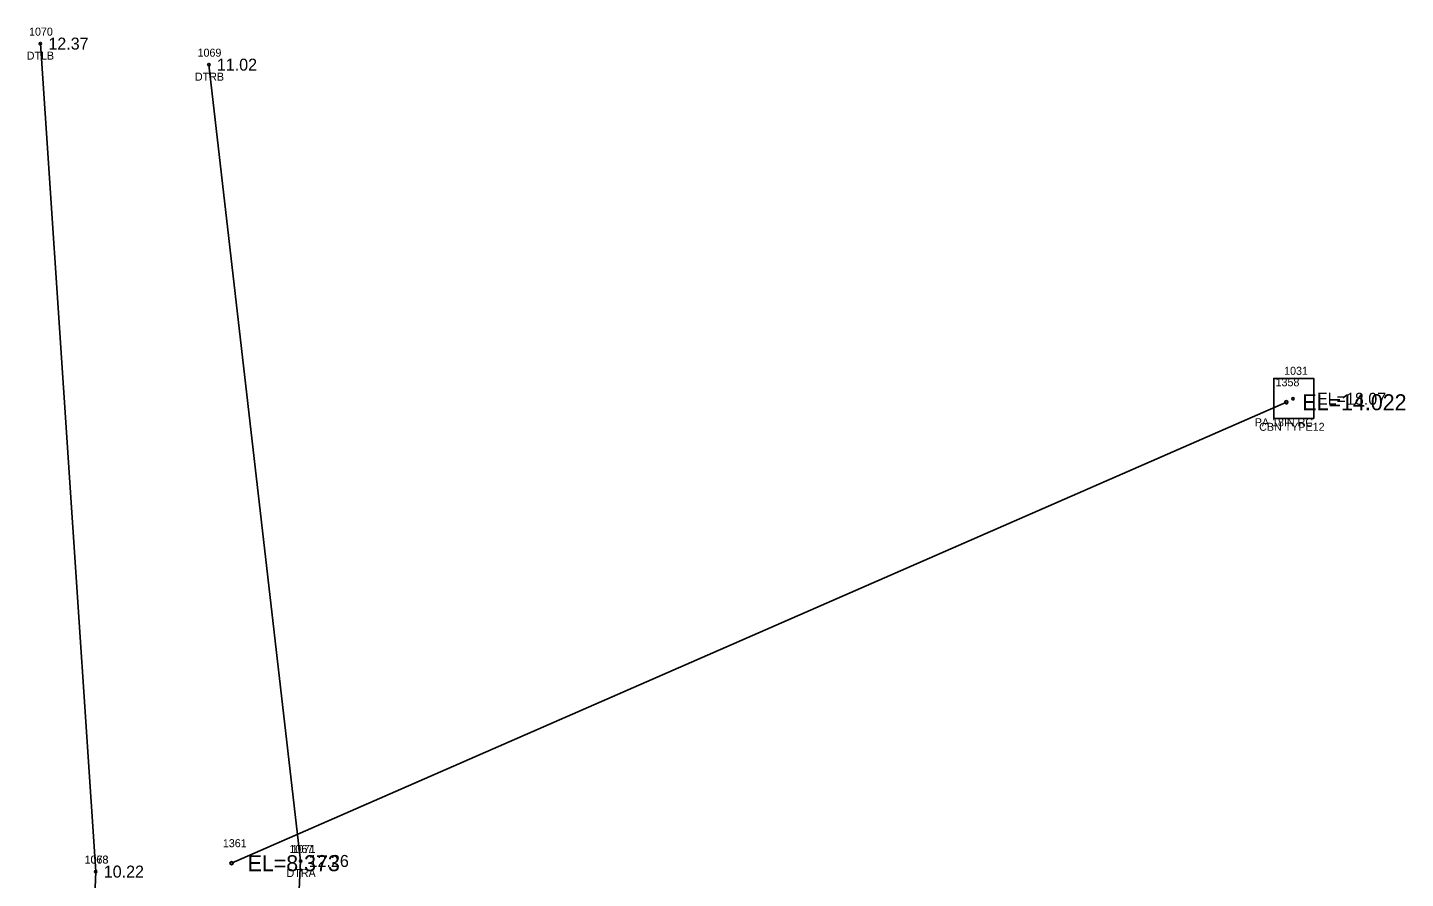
# Model space of a CAD drawing. Extents: x 2072307 to 2072993, y 127574 to 129736.
# Drawn here: x 2072396.9 to 2072569, y 129473 to 129579.4 of the extents above; entities that cross this region are included whole.
import ezdxf

# ---------------------------------------------------------------- set-up
doc = ezdxf.new("R2010")
doc.units = 0
for name, color, linetype in [('RD_EX_DR_Inlet', 7, 'Continuous'), ('RD_EX_DR_Inlet_txCode', 7, 'Continuous'), ('RD_EX_DR_Pipe', 7, 'Continuous'), ('RD_EX_DR_Pipe_txCode', 7, 'Continuous'), ('RD_EX_H2O', 7, 'Continuous'), ('RD_EX_H2O_txCode', 7, 'Continuous'), ('RD_EX_TX_DR_Inlet_ELEV', 7, 'Continuous'), ('RD_EX_TX_H2O_ELEV', 7, 'Continuous'), ('RD_SMD_Locator', 7, 'Continuous'), ('RD_TX_Pipe_ElevEX', 7, 'Continuous')]:
    doc.layers.add(name, color=color, linetype=linetype)

msp = doc.modelspace()

# ---------------------------------------------------------------- linework, layer by layer
at = {"layer": 'RD_EX_DR_Inlet'}
msp.add_line((2072557.59, 129530.55), (2072557.59, 129535.55), dxfattribs=at)
msp.add_lwpolyline([(2072557.59, 129530.55), (2072557.59, 129535.55), (2072552.59, 129535.55), (2072552.59, 129530.55)], close=True, dxfattribs=at)
at = {"layer": 'RD_EX_DR_Pipe'}
msp.add_line((2072554.17, 129532.57), (2072422.36, 129474.95), dxfattribs=at)
at = {"layer": 'RD_EX_H2O'}
for p, q in [((2072405.39, 129473.9), (2072398.47, 129577.4)), ((2072430.99, 129475.23), (2072419.52, 129574.77))]:
    msp.add_line(p, q, dxfattribs=at)
for points in [[(2072430.99, 129475.23), (2072426.01, 129368.3), (2072422.66, 129295.95), (2072416.7, 129153.3), (2072414.39, 129056.34)], [(2072405.39, 129473.9), (2072401.06, 129369.87), (2072405.35, 129295.82), (2072402.29, 129156.96), (2072397.22, 129166.67)]]:
    msp.add_lwpolyline(points, dxfattribs=at)
at = {"layer": 'RD_SMD_Locator'}
for centre, radius in [((2072398.47, 129577.4), 0.15), ((2072419.52, 129574.77), 0.15), ((2072554.17, 129532.57), 0.2), ((2072554.99, 129533), 0.15), ((2072430.99, 129475.23), 0.15), ((2072430.99, 129475.23), 0.15), ((2072405.39, 129473.9), 0.15), ((2072405.39, 129473.9), 0.15), ((2072422.36, 129474.95), 0.2)]:
    msp.add_circle(centre, radius, dxfattribs=at)

# ---------------------------------------------------------------- texts
at = {"layer": 'RD_EX_DR_Inlet_txCode'}
for s, p in [('1031', (2072553.89, 129536)), ('CBN TYPE12', (2072550.77, 129529))]:
    msp.add_text(s, height=1, dxfattribs=at).set_placement(p)
at = {"layer": 'RD_EX_DR_Pipe_txCode'}
for s, p in [('1358', (2072552.82, 129534.57)), ('PA 18IN RC', (2072550.22, 129529.57)), ('1361', (2072421.27, 129476.95))]:
    msp.add_text(s, height=1, dxfattribs=at).set_placement(p)
at = {"layer": 'RD_EX_H2O_txCode'}
for s, p in [('1070', (2072397.05, 129578.4)), ('DTLB', (2072396.76, 129575.4)), ('1069', (2072418.11, 129575.77)), ('DTRB', (2072417.78, 129572.77)), ('1067', (2072429.58, 129476.23)), ('1071', (2072429.88, 129476.23)), ('1068', (2072403.98, 129474.9)), ('1073', (2072404.01, 129474.9)), ('DTRA', (2072429.23, 129473.23)), ('DTRA', (2072429.23, 129473.23))]:
    msp.add_text(s, height=1, dxfattribs=at).set_placement(p)
at = {"layer": 'RD_EX_TX_DR_Inlet_ELEV'}
msp.add_text('EL=18.07', height=1.5, dxfattribs=at).set_placement((2072557.99, 129532.25))
at = {"layer": 'RD_EX_TX_H2O_ELEV'}
for s, p in [('12.37', (2072399.47, 129576.65)), ('11.02', (2072420.52, 129574.02)), ('12.26', (2072431.99, 129474.48)), ('12.26', (2072431.99, 129474.48)), ('10.22', (2072406.39, 129473.15)), ('10.22', (2072406.39, 129473.15))]:
    msp.add_text(s, height=1.5, dxfattribs=at).set_placement(p)
at = {"layer": 'RD_TX_Pipe_ElevEX'}
for s, p in [('EL=14.022', (2072556.17, 129531.57)), ('EL=8.373', (2072424.36, 129473.95))]:
    msp.add_text(s, height=2, dxfattribs=at).set_placement(p)

doc.saveas('drawing.dxf')
